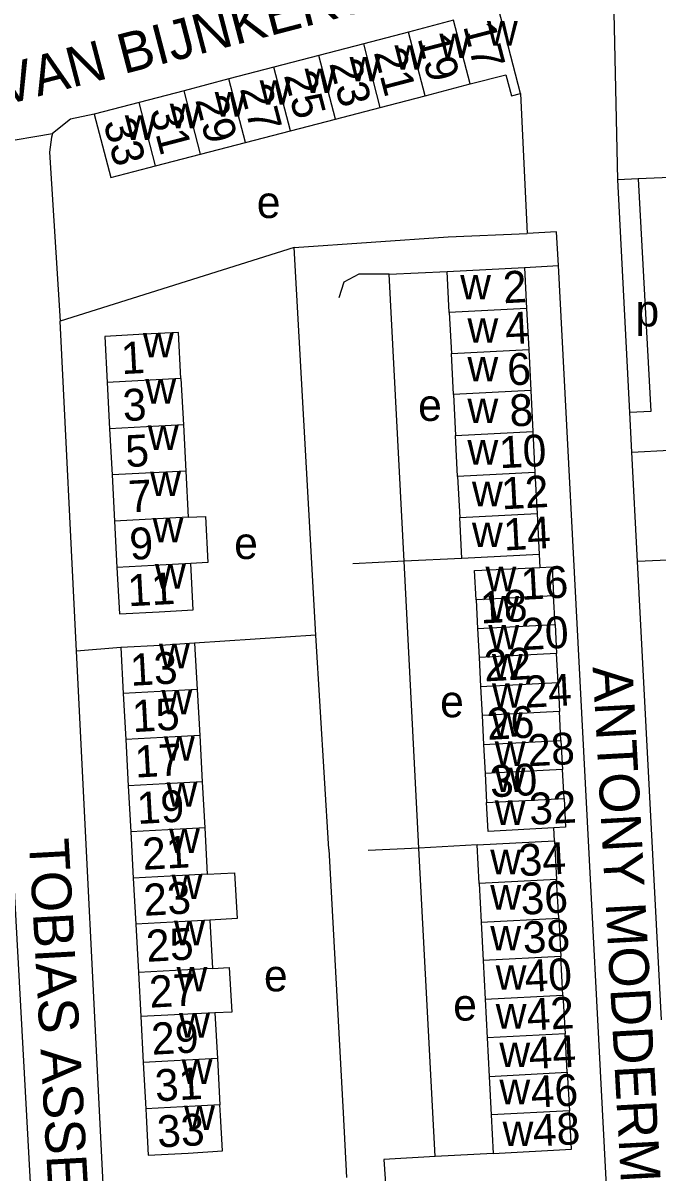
# Model space of a CAD drawing. Extents: x 157569 to 159501, y 382907 to 384670.
# Drawn here: x 158813.1 to 158892.8, y 383492.8 to 383637.3 of the extents above; entities that cross this region are included whole.
import ezdxf

# ---------------------------------------------------------------- set-up
doc = ezdxf.new("R2010")
doc.units = 0
for name, color, linetype in [('BLT_Basislijn', 7, 'Continuous'), ('BLT_Bebouwing', 7, 'Continuous'), ('BLT_Centroide', 7, 'Continuous'), ('BLT_Huisnummer', 7, 'Continuous'), ('BLT_Huisnummer_ tussenligend', 7, 'Continuous'), ('BLT_Onderverdeling_panden', 7, 'Continuous'), ('BLT_Straatnaam', 7, 'Continuous'), ('BLT_Vlakafsluiter', 7, 'Continuous')]:
    doc.layers.add(name, color=color, linetype=linetype)

msp = doc.modelspace()

# ---------------------------------------------------------------- linework, layer by layer
at = {"layer": 'BLT_Basislijn'}
for p, q in [((158887.75, 383617.55), (158887.21, 383642.78)), ((158875.56, 383628.4), (158876.38, 383610.8)), ((158890.33, 383617.66), (158887.75, 383617.55)), ((158889.27, 383588.31), (158887.75, 383617.55)), ((158895.33, 383617.87), (158890.33, 383617.66)), ((158847.15, 383609.03), (158817.75, 383599.79)), ((158848.99, 383576.13), (158847.15, 383609.03)), ((158876.05, 383606.54), (158880.3, 383606.77)), ((158890.34, 383414.32), (158880.3, 383606.77)), ((158855.25, 383605.69), (158853.38, 383604.7)), ((158859.07, 383605.69), (158855.25, 383605.69)), ((158859.07, 383605.69), (158866.34, 383606.04)), ((158860.94, 383569.62), (158859.07, 383605.69)), ((158853.38, 383604.7), (158852.73, 383602.73)), ((158819.84, 383558.34), (158817.75, 383599.79)), ((158889.53, 383583.33), (158889.27, 383588.31)), ((158889.53, 383583.33), (158894.24, 383583.58)), ((158890.25, 383569.6), (158889.53, 383583.33)), ((158849.85, 383560.35), (158848.99, 383576.13)), ((158877.9, 383570.47), (158877.98, 383568.86)), ((158860.94, 383569.62), (158854.51, 383569.32)), ((158868.19, 383569.96), (158860.94, 383569.62)), ((158862.81, 383533.6), (158860.94, 383569.62)), ((158894.95, 383569.81), (158890.25, 383569.6)), ((158893.25, 383512.02), (158890.25, 383569.6)), ((158849.85, 383560.35), (158834.65, 383559.33)), ((158851.48, 383533.45), (158849.85, 383560.35)), ((158825.38, 383558.78), (158819.84, 383558.34)), ((158823.21, 383490.59), (158819.84, 383558.34)), ((158879.81, 383534.51), (158879.72, 383536.14)), ((158851.48, 383533.45), (158853.29, 383500.32)), ((158862.81, 383533.6), (158856.45, 383533.27)), ((158870.1, 383533.98), (158862.81, 383533.6)), ((158864.82, 383494.86), (158862.81, 383533.6)), ((158853.29, 383500.32), (158853.7, 383492.22)), ((158872.1, 383495.22), (158864.82, 383494.86)), ((158864.82, 383494.86), (158858.4, 383494.45)), ((158858.4, 383494.45), (158858.68, 383490.22))]:
    msp.add_line(p, q, dxfattribs=at)
for points in [[(158822.03, 383625.8), (158819.07, 383625.15), (158816.79, 383623.36)], [(158816.79, 383623.36), (158816.67, 383622.89), (158816.42, 383621.03), (158817.75, 383599.79)], [(158806.83, 383621.66), (158819.46, 383392.01), (158819.71, 383391.92), (158819.2, 383390.12), (158817.89, 383389.1)], [(158890.33, 383617.66), (158891.91, 383588.45), (158889.27, 383588.31)], [(158847.15, 383609.03), (158866.48, 383610.39), (158876.38, 383610.8)], [(158880.3, 383606.77), (158880.08, 383611.02), (158876.38, 383610.8)]]:
    msp.add_lwpolyline(points, dxfattribs=at)
at = {"layer": 'BLT_Bebouwing'}
for p, q in [((158875.56, 383628.4), (158872.77, 383639.07)), ((158867.14, 383637.6), (158861.5, 383636.12)), ((158861.5, 383636.12), (158855.87, 383634.65)), ((158855.87, 383634.65), (158850.23, 383633.18)), ((158850.23, 383633.18), (158844.59, 383631.7)), ((158844.59, 383631.7), (158838.95, 383630.23)), ((158838.95, 383630.23), (158833.32, 383628.75)), ((158863.59, 383628.12), (158869.23, 383629.59)), ((158833.32, 383628.75), (158827.68, 383627.28)), ((158827.68, 383627.28), (158822.03, 383625.8)), ((158857.95, 383626.65), (158863.59, 383628.12)), ((158852.31, 383625.18), (158857.95, 383626.65)), ((158846.67, 383623.72), (158852.31, 383625.18)), ((158841.03, 383622.24), (158846.67, 383623.72)), ((158835.39, 383620.78), (158841.03, 383622.24)), ((158829.75, 383619.31), (158835.39, 383620.78)), ((158866.34, 383606.04), (158876.05, 383606.54)), ((158876.05, 383606.54), (158876.32, 383601.39)), ((158866.6, 383600.89), (158866.34, 383606.04)), ((158866.6, 383600.89), (158866.87, 383595.73)), ((158876.32, 383601.39), (158876.58, 383596.23)), ((158867.13, 383590.58), (158866.87, 383595.73)), ((158876.58, 383596.23), (158876.84, 383591.08)), ((158823.68, 383592.09), (158823.98, 383586.28)), ((158832.93, 383592.58), (158833.23, 383586.77)), ((158867.13, 383590.58), (158867.39, 383585.42)), ((158876.84, 383591.08), (158877.11, 383585.92)), ((158823.98, 383586.28), (158824.28, 383580.48)), ((158833.23, 383586.77), (158833.54, 383580.96)), ((158867.66, 383580.27), (158867.39, 383585.42)), ((158877.11, 383585.92), (158877.37, 383580.77)), ((158824.28, 383580.48), (158824.59, 383574.67)), ((158833.54, 383580.96), (158833.85, 383575.16)), ((158877.37, 383580.77), (158877.63, 383575.61)), ((158867.66, 383580.27), (158867.92, 383575.11)), ((158824.59, 383574.67), (158824.89, 383568.86)), ((158868.19, 383569.96), (158867.92, 383575.11)), ((158877.63, 383575.61), (158877.9, 383570.47)), ((158877.9, 383570.47), (158868.19, 383569.96)), ((158877.98, 383568.86), (158879.51, 383568.93)), ((158879.51, 383568.93), (158879.7, 383565.3)), ((158869.79, 383568.45), (158877.98, 383568.86)), ((158869.98, 383564.8), (158869.79, 383568.45)), ((158869.98, 383564.8), (158870.17, 383561.16)), ((158879.89, 383561.66), (158879.7, 383565.3)), ((158879.89, 383561.66), (158880.08, 383558.02)), ((158870.17, 383561.16), (158870.36, 383557.52)), ((158825.38, 383558.78), (158825.69, 383553.02)), ((158834.65, 383559.33), (158834.97, 383553.53)), ((158870.36, 383557.52), (158870.54, 383553.88)), ((158880.27, 383554.38), (158880.08, 383558.02)), ((158825.69, 383553.02), (158826, 383547.22)), ((158834.97, 383553.53), (158835.29, 383547.73)), ((158870.54, 383553.88), (158870.73, 383550.23)), ((158880.27, 383554.38), (158880.46, 383550.74)), ((158870.73, 383550.23), (158870.92, 383546.59)), ((158880.63, 383547.09), (158880.46, 383550.74)), ((158826, 383547.22), (158826.32, 383541.42)), ((158835.29, 383547.73), (158835.61, 383541.93)), ((158870.92, 383546.59), (158871.11, 383542.95)), ((158880.63, 383547.09), (158880.83, 383543.45)), ((158871.11, 383542.95), (158871.3, 383539.31)), ((158881.02, 383539.81), (158880.83, 383543.45)), ((158835.61, 383541.93), (158835.92, 383536.13)), ((158826.32, 383541.42), (158826.63, 383535.62)), ((158871.49, 383535.66), (158871.3, 383539.31)), ((158881.02, 383539.81), (158881.21, 383536.23)), ((158835.92, 383536.13), (158836.24, 383530.33)), ((158879.72, 383536.14), (158871.49, 383535.66)), ((158881.21, 383536.23), (158879.72, 383536.14)), ((158826.63, 383535.62), (158826.95, 383529.83)), ((158870.1, 383533.98), (158879.81, 383534.51)), ((158879.81, 383534.51), (158880.08, 383529.64)), ((158870.35, 383529.14), (158870.1, 383533.98)), ((158826.95, 383529.83), (158827.26, 383524.03)), ((158870.35, 383529.14), (158870.6, 383524.29)), ((158880.35, 383524.8), (158880.08, 383529.64)), ((158836.56, 383524.54), (158836.89, 383518.46)), ((158870.6, 383524.29), (158870.85, 383519.45)), ((158880.35, 383524.8), (158880.62, 383519.95)), ((158827.26, 383524.03), (158827.59, 383517.95)), ((158880.88, 383515.11), (158880.62, 383519.95)), ((158870.85, 383519.45), (158871.1, 383514.6)), ((158827.59, 383517.95), (158827.89, 383512.43)), ((158871.1, 383514.6), (158871.35, 383509.76)), ((158880.88, 383515.11), (158881.15, 383510.27)), ((158837.19, 383512.88), (158837.51, 383507.14)), ((158827.89, 383512.43), (158828.2, 383506.63)), ((158871.35, 383509.76), (158871.6, 383504.91)), ((158881.42, 383505.42), (158881.15, 383510.27)), ((158837.51, 383507.14), (158837.83, 383501.34)), ((158828.2, 383506.63), (158828.52, 383500.83)), ((158881.42, 383505.42), (158881.69, 383500.58)), ((158871.6, 383504.91), (158871.85, 383500.07)), ((158871.85, 383500.07), (158872.1, 383495.22)), ((158881.96, 383495.75), (158881.69, 383500.58)), ((158872.1, 383495.22), (158881.96, 383495.75))]:
    msp.add_line(p, q, dxfattribs=at)
for points in [[(158869.23, 383629.59), (158873.72, 383630.76), (158874.42, 383628.1), (158875.56, 383628.4)], [(158822.03, 383625.8), (158824.12, 383617.84), (158828.95, 383619.1), (158829.75, 383619.31)], [(158832.93, 383592.58), (158832.62, 383598.38), (158828.37, 383598.14), (158823.37, 383597.88), (158823.68, 383592.09)], [(158833.85, 383575.16), (158836.01, 383575.25), (158836.32, 383569.49), (158834.15, 383569.35)], [(158824.89, 383568.86), (158825.2, 383563), (158830.19, 383563.26), (158834.46, 383563.54), (158834.15, 383569.35)], [(158834.65, 383559.33), (158830.37, 383559.05), (158825.38, 383558.78)], [(158836.24, 383530.33), (158839.67, 383530.5), (158839.99, 383524.75), (158836.56, 383524.54)], [(158836.89, 383518.46), (158838.99, 383518.57), (158839.3, 383512.99), (158837.19, 383512.88)], [(158828.52, 383500.83), (158828.56, 383500), (158828.83, 383495), (158833.83, 383495.27), (158838.14, 383495.54), (158837.9, 383500), (158837.83, 383501.34)]]:
    msp.add_lwpolyline(points, dxfattribs=at)
at = {"layer": 'BLT_Onderverdeling_panden'}
for p, q in [((158869.23, 383629.59), (158867.14, 383637.6)), ((158863.59, 383628.12), (158861.5, 383636.12)), ((158857.95, 383626.65), (158855.87, 383634.65)), ((158852.31, 383625.18), (158850.23, 383633.18)), ((158846.67, 383623.72), (158844.59, 383631.7)), ((158841.03, 383622.24), (158838.95, 383630.23)), ((158835.39, 383620.78), (158833.32, 383628.75)), ((158829.75, 383619.31), (158827.68, 383627.28)), ((158876.32, 383601.39), (158866.6, 383600.89)), ((158866.87, 383595.73), (158876.58, 383596.23)), ((158832.93, 383592.58), (158823.68, 383592.09)), ((158876.84, 383591.08), (158867.13, 383590.58)), ((158833.23, 383586.77), (158823.98, 383586.28)), ((158867.39, 383585.42), (158877.11, 383585.92)), ((158833.54, 383580.96), (158824.28, 383580.48)), ((158877.37, 383580.77), (158867.66, 383580.27)), ((158833.85, 383575.16), (158824.59, 383574.67)), ((158867.92, 383575.11), (158877.63, 383575.61)), ((158834.15, 383569.35), (158824.89, 383568.86)), ((158879.7, 383565.3), (158869.98, 383564.8)), ((158870.17, 383561.16), (158879.89, 383561.66)), ((158880.08, 383558.02), (158870.36, 383557.52)), ((158834.97, 383553.53), (158825.69, 383553.02)), ((158870.54, 383553.88), (158880.27, 383554.38)), ((158880.46, 383550.74), (158870.73, 383550.23)), ((158835.29, 383547.73), (158826, 383547.22)), ((158870.92, 383546.59), (158880.63, 383547.09)), ((158880.83, 383543.45), (158871.11, 383542.95)), ((158835.61, 383541.93), (158826.32, 383541.42)), ((158871.3, 383539.31), (158881.02, 383539.81)), ((158835.92, 383536.13), (158826.63, 383535.62)), ((158836.24, 383530.33), (158826.95, 383529.83)), ((158880.08, 383529.64), (158870.35, 383529.14)), ((158836.56, 383524.54), (158827.26, 383524.03)), ((158870.6, 383524.29), (158880.35, 383524.8)), ((158880.62, 383519.95), (158870.85, 383519.45)), ((158836.89, 383518.46), (158827.59, 383517.95)), ((158871.1, 383514.6), (158880.88, 383515.11)), ((158837.19, 383512.88), (158827.89, 383512.43)), ((158881.15, 383510.27), (158871.35, 383509.76)), ((158837.51, 383507.14), (158828.2, 383506.63)), ((158871.6, 383504.91), (158881.42, 383505.42)), ((158837.83, 383501.34), (158828.52, 383500.83)), ((158881.69, 383500.58), (158871.85, 383500.07))]:
    msp.add_line(p, q, dxfattribs=at)
at = {"layer": 'BLT_Vlakafsluiter'}
msp.add_line((158806.83, 383621.66), (158816.79, 383623.36), dxfattribs=at)

# ---------------------------------------------------------------- texts
at = {"layer": 'BLT_Centroide'}
for s, p in [('w', (158871.34, 383634.42)), ('w', (158865.36, 383632.86)), ('w', (158859.73, 383631.39)), ('w', (158854.09, 383629.92)), ('w', (158848.45, 383628.45)), ('w', (158842.81, 383626.98)), ('w', (158837.17, 383625.5)), ('w', (158831.53, 383624.03)), ('w', (158825.89, 383622.56)), ('e', (158842.45, 383612.75)), ('w', (158867.98, 383602.53)), ('p', (158889.98, 383599.13)), ('w', (158868.89, 383597.08)), ('w', (158828.15, 383595.25)), ('w', (158868.89, 383592.23)), ('w', (158828.45, 383589.44)), ('e', (158862.7, 383587.26)), ('w', (158868.89, 383586.98)), ('w', (158828.77, 383583.62)), ('w', (158868.89, 383581.77)), ('w', (158829.06, 383577.81)), ('w', (158869.46, 383576.54)), ('w', (158829.37, 383572)), ('w', (158869.46, 383571.4)), ('e', (158839.61, 383569.91)), ('w', (158829.67, 383566.19)), ('w', (158871.16, 383565.86)), ('w', (158871.52, 383562.21)), ('w', (158871.52, 383558.54)), ('w', (158830.17, 383556.19)), ('w', (158871.97, 383554.9)), ('w', (158830.48, 383550.38)), ('e', (158865.46, 383550.03)), ('w', (158871.97, 383551.23)), ('w', (158871.97, 383547.57)), ('w', (158830.8, 383544.56)), ('w', (158872.32, 383543.91)), ('w', (158872.32, 383540.64)), ('w', (158831.12, 383538.78)), ('w', (158872.32, 383536.5)), ('w', (158831.44, 383532.97)), ('w', (158871.76, 383530.3)), ('w', (158831.76, 383527.19)), ('w', (158871.76, 383525.86)), ('w', (158832.07, 383521.38)), ('w', (158871.76, 383520.74)), ('w', (158832.38, 383515.59)), ('e', (158843.35, 383515.59)), ('w', (158872.44, 383515.8)), ('e', (158867.1, 383511.92)), ('w', (158872.44, 383510.92)), ('w', (158832.7, 383509.78)), ('w', (158872.9, 383506.07)), ('w', (158833.02, 383503.97)), ('w', (158872.9, 383501.41)), ('w', (158833.33, 383498.16)), ('w', (158873.3, 383496.15))]:
    msp.add_text(s, height=4, dxfattribs=at).set_placement(p)
at = {"layer": 'BLT_Huisnummer'}
for s, rotation, p in [('17', 284.5999, (158868.33, 383636.86)), ('21', 284.6086, (158857.11, 383633.57)), ('25', 284.606, (158845.83, 383630.69)), ('29', 284.606, (158834.7, 383627.6)), ('33', 284.606, (158823.18, 383624.76)), ('2', 3.0105, (158873.45, 383602.03)), ('1', 3.0105, (158825.5, 383593.13)), ('6', 3.0105, (158873.98, 383591.7)), ('5', 3.0105, (158826.04, 383581.44)), ('10', 3.0105, (158872.95, 383581.3)), ('14', 3.0105, (158873.49, 383570.97)), ('16', 3.0105, (158875.69, 383564.77)), ('11', 3.0105, (158826.33, 383563.96)), ('20', 3.0105, (158875.74, 383558.45)), ('13', 3.1316, (158826.65, 383553.97)), ('24', 3.0105, (158876.12, 383551.21)), ('28', 3.0105, (158876.51, 383543.85)), ('17', 3.1316, (158827.23, 383542.44)), ('32', 3.0105, (158876.73, 383536.5)), ('21', 3.1316, (158828.19, 383530.85)), ('34', 3.0105, (158875.4, 383530.05)), ('38', 3.0105, (158875.92, 383520.35)), ('25', 3.1316, (158828.66, 383519.29)), ('42', 3.0105, (158876.43, 383510.65)), ('29', 3.1316, (158829.31, 383507.62)), ('33', 3.1316, (158830.04, 383495.96)), ('48', 3.0105, (158877.19, 383496.09))]:
    msp.add_text(s, height=4, rotation=rotation, dxfattribs=at).set_placement(p)
at = {"layer": 'BLT_Huisnummer_ tussenligend'}
for s, rotation, p in [('19', 284.5999, (158862.6, 383635.35)), ('23', 284.6086, (158851.52, 383632.18)), ('27', 284.606, (158840.3, 383629.01)), ('31', 284.606, (158828.96, 383626.25)), ('4', 3.0105, (158873.71, 383596.86)), ('3', 3.0105, (158825.72, 383587.22)), ('8', 3.0105, (158874.26, 383586.54)), ('12', 3.0105, (158873.23, 383576.14)), ('7', 3.0105, (158826.42, 383575.75)), ('9', 3.0105, (158826.57, 383569.79)), ('18', 3.0105, (158870.57, 383561.8)), ('22', 3.0105, (158871.06, 383554.52)), ('15', 3.1316, (158826.91, 383548.15)), ('26', 3.0105, (158871.43, 383547.18)), ('30', 3.0105, (158871.81, 383539.96)), ('19', 3.1316, (158827.5, 383536.61)), ('23', 3.1316, (158828.33, 383525.07)), ('36', 3.0105, (158875.65, 383525.2)), ('40', 3.0105, (158876.16, 383515.5)), ('27', 3.1316, (158829.05, 383513.53)), ('44', 3.0105, (158876.67, 383505.8)), ('31', 3.1316, (158829.77, 383501.76)), ('46', 3.0105, (158876.93, 383500.94))]:
    msp.add_text(s, height=4, rotation=rotation, dxfattribs=at).set_placement(p)
at = {"layer": 'BLT_Straatnaam'}
for s, height, rotation, p in [('CORNELIS VAN BIJNKERSHOEKSTRAAT', 4.9999, 14.6494, (158775.77, 383617.75)), ('ANTONY MODDERMANSTRAAT', 4.9999, 273.1448, (158884.6, 383556.33)), ('TOBIAS ASSERSTRAAT', 5, 273.1822, (158813.83, 383534.67))]:
    msp.add_text(s, height=height, rotation=rotation, dxfattribs=at).set_placement(p)

doc.saveas('drawing.dxf')
